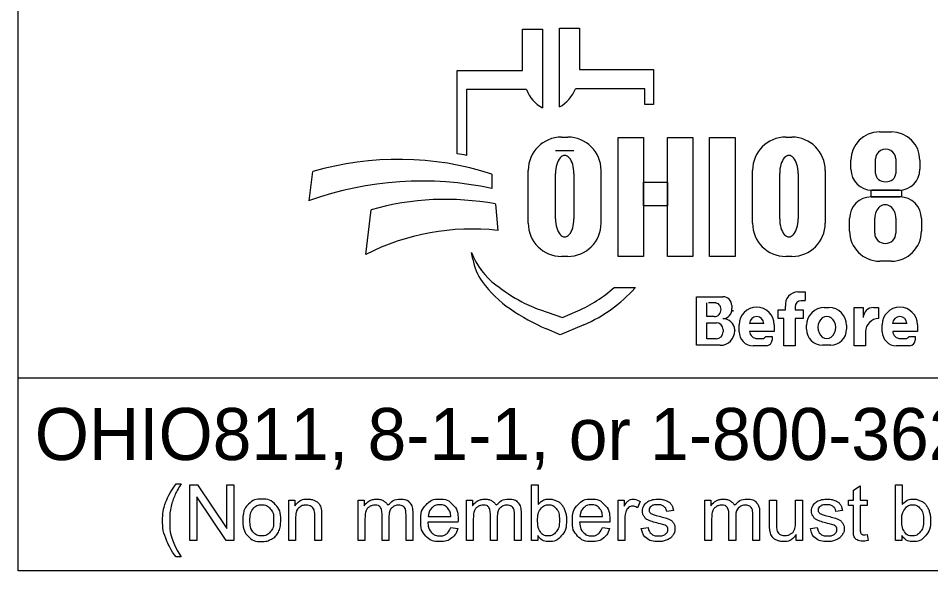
# Model space of a CAD drawing. Extents: x 0 to 45, y -99 to 22.
# Drawn here: x 2.978 to 5.431, y 2.462 to 3.948 of the extents above; entities that cross this region are included whole.
import ezdxf

# ---------------------------------------------------------------- set-up
doc = ezdxf.new("R2010")
doc.units = 0
doc.layers.add('SH_Cut_Line', color=7, linetype='Continuous')
doc.layers.add('SH_Text', color=7, linetype='Continuous')

msp = doc.modelspace()

# ---------------------------------------------------------------- linework, layer by layer
at = {"layer": 'SH_Cut_Line'}
for p, q in [((2.9775, 2.4619), (2.9775, 4.7994)), ((7.2275, 2.9798), (2.9775, 2.9798)), ((7.2275, 2.4619), (2.9775, 2.4619))]:
    msp.add_line(p, q, dxfattribs=at)
at = {"layer": 'SH_Text'}
for p, q in [((4.3335, 3.8074), (4.3335, 3.9189)), ((4.3335, 3.9189), (4.3872, 3.9189)), ((4.3872, 3.9189), (4.3872, 3.7068)), ((4.4329, 3.7092), (4.4329, 3.9212)), ((4.4329, 3.9212), (4.4865, 3.9212)), ((4.4865, 3.9212), (4.4865, 3.8097)), ((4.1576, 3.5835), (4.1576, 3.8074)), ((4.1576, 3.8074), (4.3335, 3.8074)), ((4.4865, 3.8097), (4.6857, 3.8097)), ((4.6857, 3.8097), (4.6857, 3.7159)), ((4.1828, 3.756), (4.1828, 3.5791)), ((4.3439, 3.756), (4.1828, 3.756)), ((4.6625, 3.7583), (4.4761, 3.7583)), ((4.6625, 3.7159), (4.6625, 3.7583)), ((4.6857, 3.7159), (4.6625, 3.7159)), ((5.2931, 3.6422), (5.3258, 3.6422)), ((4.4385, 3.6282), (4.4551, 3.6282)), ((5.0416, 3.6282), (5.0581, 3.6282)), ((4.4718, 3.5912), (4.422, 3.5912)), ((5.2168, 3.5416), (5.2168, 3.5659)), ((5.283, 3.5302), (5.283, 3.5695)), ((5.3371, 3.5695), (5.3371, 3.5302)), ((5.4022, 3.5659), (5.4022, 3.5416)), ((3.7602, 3.4572), (3.7696, 3.5353)), ((4.3491, 3.3967), (4.3491, 3.5388)), ((4.5445, 3.5388), (4.5445, 3.3967)), ((4.9521, 3.3967), (4.9521, 3.5388)), ((5.1476, 3.5388), (5.1476, 3.3967)), ((4.2509, 3.5289), (4.2509, 3.49)), ((4.422, 3.4081), (4.422, 3.5305)), ((4.4718, 3.5305), (4.4718, 3.4081)), ((5.025, 3.4081), (5.025, 3.5305)), ((5.0748, 3.5305), (5.0748, 3.4081)), ((5.3462, 3.4856), (5.2728, 3.4856)), ((5.271, 3.4673), (5.3483, 3.4673)), ((4.2608, 3.4482), (4.2671, 3.3773)), ((3.912, 3.3127), (3.9267, 3.4328)), ((5.2131, 3.3754), (5.2131, 3.4094)), ((5.2806, 3.3694), (5.2806, 3.4103)), ((5.3374, 3.4103), (5.3374, 3.3694)), ((5.4062, 3.4094), (5.4062, 3.3754)), ((4.1997, 3.2998), (4.1967, 3.3177)), ((4.4551, 3.3073), (4.4385, 3.3073)), ((5.0581, 3.3073), (5.0416, 3.3073)), ((5.3252, 3.2944), (5.2941, 3.2944)), ((4.58, 3.2239), (4.6375, 3.2239)), ((4.8013, 3.0682), (4.8013, 3.1989)), ((4.8013, 3.1989), (4.8725, 3.1989)), ((5.0739, 3.2117), (5.0934, 3.2117)), ((5.0934, 3.2117), (5.0934, 3.1887)), ((4.8293, 3.1454), (4.8293, 3.1823)), ((4.8545, 3.1823), (4.8332, 3.1823)), ((4.8963, 3.1751), (4.8963, 3.1672)), ((5.0406, 3.1633), (5.0406, 3.1737)), ((5.0667, 3.1717), (5.0667, 3.1633)), ((5.0934, 3.1882), (5.0832, 3.1882)), ((5.1451, 3.1699), (5.1573, 3.1699)), ((5.2254, 3.067), (5.2254, 3.1696)), ((5.2254, 3.1696), (5.2499, 3.1696)), ((5.2499, 3.1696), (5.2499, 3.1428)), ((5.2772, 3.1696), (5.291, 3.1696)), ((5.291, 3.1696), (5.291, 3.14)), ((4.3816, 3.1635), (4.441, 3.143)), ((4.441, 3.143), (4.4821, 3.1609)), ((4.8487, 3.1454), (4.8293, 3.1454)), ((5.0213, 3.1403), (5.0213, 3.1633)), ((5.0213, 3.1633), (5.0406, 3.1633)), ((5.0667, 3.1633), (5.0883, 3.1633)), ((5.0883, 3.1633), (5.0883, 3.1403)), ((4.4983, 3.1235), (4.435, 3.096)), ((4.8293, 3.086), (4.8293, 3.1288)), ((4.8293, 3.1288), (4.8548, 3.1288)), ((4.9159, 3.1049), (4.9159, 3.1234)), ((4.9824, 3.1273), (4.9439, 3.1273)), ((5.0104, 3.1234), (5.0104, 3.1057)), ((5.0362, 3.1403), (5.0213, 3.1403)), ((5.0362, 3.067), (5.0362, 3.1403)), ((5.0883, 3.1403), (5.0667, 3.1403)), ((5.0667, 3.1403), (5.0667, 3.067)), ((5.0973, 3.1113), (5.0973, 3.1221)), ((5.2051, 3.1221), (5.2051, 3.1113)), ((5.3008, 3.1049), (5.3008, 3.1234)), ((5.3674, 3.1273), (5.3288, 3.1273)), ((5.3953, 3.1234), (5.3953, 3.1057)), ((4.435, 3.096), (4.3976, 3.1125)), ((4.8729, 3.1107), (4.8729, 3.1044)), ((4.9043, 3.1078), (4.9043, 3.1075)), ((5.0104, 3.1057), (4.944, 3.1057)), ((4.9876, 3.092), (5.0045, 3.092)), ((5.0045, 3.092), (5.0045, 3.0822)), ((5.2559, 3.1051), (5.2559, 3.067)), ((5.3953, 3.1057), (5.3289, 3.1057)), ((5.3725, 3.092), (5.3894, 3.092)), ((5.3894, 3.092), (5.3894, 3.0822)), ((4.865, 3.0682), (4.8013, 3.0682)), ((4.8546, 3.086), (4.8293, 3.086)), ((4.9649, 3.0864), (4.979, 3.0864)), ((5.1623, 3.0685), (5.1401, 3.0685)), ((5.3498, 3.0864), (5.3639, 3.0864)), ((4.9892, 3.067), (4.9538, 3.067)), ((5.0667, 3.067), (5.0362, 3.067)), ((5.2559, 3.067), (5.2254, 3.067)), ((5.3742, 3.067), (5.3388, 3.067))]:
    msp.add_line(p, q, dxfattribs=at)
for points in [[(4.591, 3.6272), (4.6589, 3.6272), (4.6589, 3.3072), (4.591, 3.3072)], [(4.7231, 3.6272), (4.7911, 3.6272), (4.7911, 3.3072), (4.7231, 3.3072)], [(4.8364, 3.6272), (4.9052, 3.6272), (4.9052, 3.3072), (4.8364, 3.3072)], [(4.6589, 3.5073), (4.7231, 3.5073), (4.7231, 3.4433), (4.6589, 3.4433)], [(5.2706, 3.4857), (5.3523, 3.4857), (5.3523, 3.4672), (5.2706, 3.4672)]]:
    msp.add_lwpolyline(points, close=True, dxfattribs=at)
for points in [[(3.4021, 2.6957), (3.4153, 2.6957)], [(3.4389, 2.543), (3.4389, 2.6932), (3.4592, 2.6932), (3.5382, 2.5753), (3.5382, 2.6932), (3.5572, 2.6932), (3.5572, 2.543), (3.5369, 2.543), (3.4579, 2.661), (3.4579, 2.543), (3.4389, 2.543)], [(4.3743, 2.543), (4.3573, 2.543), (4.3573, 2.6932), (4.3757, 2.6932), (4.3757, 2.6397)], [(5.2233, 2.5749), (5.2233, 2.6376), (5.2097, 2.6376), (5.2097, 2.6519), (5.2233, 2.6519), (5.2233, 2.6788), (5.2417, 2.6899), (5.2417, 2.6519), (5.2601, 2.6519), (5.2601, 2.6376), (5.2417, 2.6376), (5.2417, 2.5738)], [(5.3534, 2.543), (5.3363, 2.543), (5.3363, 2.6932), (5.3548, 2.6932), (5.3548, 2.6397)], [(3.7048, 2.543), (3.7048, 2.6519), (3.7214, 2.6519), (3.7214, 2.6364)], [(3.8912, 2.543), (3.8912, 2.6519), (3.9077, 2.6519), (3.9077, 2.6365)], [(4.1826, 2.543), (4.1826, 2.6519), (4.1991, 2.6519), (4.1991, 2.6365)], [(4.5904, 2.543), (4.5904, 2.6519), (4.607, 2.6519), (4.607, 2.6354)], [(4.8236, 2.543), (4.8236, 2.6519), (4.8401, 2.6519), (4.8401, 2.6365)], [(4.9979, 2.5845), (4.9979, 2.6519), (5.0164, 2.6519), (5.0164, 2.5916)], [(5.0676, 2.5936), (5.0676, 2.6519), (5.0861, 2.6519), (5.0861, 2.543), (5.0696, 2.543)], [(4.6495, 2.6484), (4.643, 2.6313)], [(3.7233, 2.6024), (3.7233, 2.543), (3.7048, 2.543)], [(3.7932, 2.6099), (3.7932, 2.543), (3.7748, 2.543), (3.7748, 2.6092)], [(3.9743, 2.6062), (3.9743, 2.543), (3.9559, 2.543), (3.9559, 2.6137)], [(4.0388, 2.6177), (4.0388, 2.543), (4.0203, 2.543), (4.0203, 2.6115)], [(4.0799, 2.6078), (4.1406, 2.6078)], [(4.2657, 2.6062), (4.2657, 2.543), (4.2473, 2.543), (4.2473, 2.6137)], [(4.3301, 2.6177), (4.3301, 2.543), (4.3117, 2.543), (4.3117, 2.6115)], [(4.4879, 2.6078), (4.5486, 2.6078)], [(4.7394, 2.6237), (4.7213, 2.6213)], [(4.9067, 2.6062), (4.9067, 2.543), (4.8883, 2.543), (4.8883, 2.6137)], [(4.9711, 2.6177), (4.9711, 2.543), (4.9527, 2.543), (4.9527, 2.6115)], [(5.194, 2.6237), (5.1759, 2.6213)], [(3.9097, 2.5994), (3.9097, 2.543), (3.8912, 2.543)], [(4.16, 2.5927), (4.0788, 2.5927)], [(4.1404, 2.5782), (4.1595, 2.5758)], [(4.201, 2.5994), (4.201, 2.543), (4.1826, 2.543)], [(4.568, 2.5927), (4.4868, 2.5927)], [(4.5484, 2.5782), (4.5675, 2.5758)], [(4.6088, 2.6), (4.6088, 2.543), (4.5904, 2.543)], [(4.653, 2.5755), (4.6712, 2.5784)], [(4.842, 2.5994), (4.842, 2.543), (4.8236, 2.543)], [(5.1076, 2.5755), (5.1258, 2.5784)], [(4.3743, 2.5567), (4.3743, 2.543)], [(5.0696, 2.543), (5.0696, 2.5591)], [(5.2601, 2.5595), (5.2628, 2.5432)], [(5.3534, 2.5567), (5.3534, 2.543)], [(3.4153, 2.4989), (3.4021, 2.4989)]]:
    msp.add_lwpolyline(points, dxfattribs=at)
for centre, radius, start, end in [((4.4353, 3.7927), 0.0985, 201.9296, 240.7469), ((4.3847, 3.7951), 0.0985, 299.2531, 338.0704), ((5.2931, 3.5659), 0.0763, 90, 180), ((5.3258, 3.5659), 0.0763, 0, 90), ((4.4385, 3.5388), 0.0895, 90, 180), ((4.4551, 3.5388), 0.0895, 0, 90), ((5.0416, 3.5388), 0.0895, 90, 180), ((5.0581, 3.5388), 0.0895, 0, 90), ((4.0295, 2.7745), 0.8191, 79.2074, 81.0007), ((3.9997, 2.7493), 0.8191, 72.1402, 106.3144), ((5.2728, 3.5416), 0.056, 180, 270), ((5.3462, 3.5416), 0.056, 270, 0), ((4.0628, 2.6182), 0.8919, 77.8238, 109.8274), ((4.1267, 2.7285), 0.7322, 79.44, 105.8467), ((5.271, 3.4094), 0.0579, 90, 180), ((5.3483, 3.4094), 0.0579, 0, 90), ((4.4385, 3.3967), 0.0895, 180, 270), ((4.4551, 3.3967), 0.0895, 270, 0), ((5.0416, 3.3967), 0.0895, 180, 270), ((5.0581, 3.3967), 0.0895, 270, 0), ((4.1987, 2.7453), 0.6357, 83.8248, 116.8021), ((5.2941, 3.3754), 0.081, 180, 270), ((5.3252, 3.3754), 0.081, 270, 0), ((4.3841, 3.3898), 0.2008, 201.0457, 232.5314), ((4.341, 3.3239), 0.1433, 189.6817, 216.0884), ((4.4747, 3.4213), 0.3088, 216.0884, 235.7167), ((4.5766, 3.641), 0.5173, 232.5314, 241.794), ((4.3387, 3.4913), 0.3602, 293.4582, 312.0712), ((4.3387, 3.4913), 0.401, 293.4582, 317.8286), ((4.8725, 3.1751), 0.0238, 0, 90), ((5.0739, 3.1781), 0.0335, 90, 187.5187), ((4.6412, 3.6656), 0.6044, 235.7167, 246.2325), ((4.4914, 3.4822), 0.3371, 241.794, 250.9821), ((4.8505, 3.1654), 0.0169, 357.8325, 90), ((4.8721, 3.1644), 0.0243, 270, 6.6529), ((4.9631, 3.1234), 0.0473, 0, 180), ((5.0832, 3.1717), 0.0165, 90, 180), ((5.1451, 3.1221), 0.0478, 90, 180), ((5.1573, 3.1221), 0.0478, 0, 90), ((5.2768, 3.1428), 0.0269, 89.2449, 180), ((5.3481, 3.1234), 0.0473, 0, 180), ((4.8487, 3.1641), 0.0187, 270, 2.0582), ((4.8827, 3.1629), 0.0175, 347.4023, 0), ((4.9632, 3.1263), 0.0193, 2.9632, 177.0368), ((5.3481, 3.1263), 0.0193, 2.9632, 177.0368), ((4.8548, 3.1107), 0.0181, 0, 90), ((4.8722, 3.108), 0.0321, 4.0748, 90), ((5.2908, 3.1051), 0.0349, 89.6033, 180), ((4.8546, 3.1044), 0.0184, 270, 0), ((4.865, 3.1075), 0.0393, 270, 0), ((4.8714, 3.1078), 0.033, 0, 11.7502), ((4.9538, 3.1049), 0.038, 180, 270), ((4.9649, 3.1074), 0.021, 184.827, 270), ((4.979, 3.0958), 0.00938, 270, 335.9979), ((5.1401, 3.1113), 0.0428, 180, 270), ((5.1623, 3.1113), 0.0428, 270, 0), ((5.3388, 3.1049), 0.038, 180, 270), ((5.3498, 3.1074), 0.021, 184.827, 270), ((5.3639, 3.0958), 0.00938, 270, 335.9979), ((4.9892, 3.0822), 0.0152, 270, 0), ((5.3742, 3.0822), 0.0152, 270, 0)]:
    msp.add_arc(centre, radius, start, end, dxfattribs=at)
for centre, major_axis, ratio, start_param, end_param in [((5.31, 3.5695), (0.0271, 0), 0.969373, 0, 3.141593), ((4.4469, 3.5305), (0, 0.0484), 0.514403, 4.712389, 7.853982), ((5.0499, 3.5305), (0, 0.0484), 0.514403, 4.712389, 7.853982), ((5.31, 3.5302), (0.0271, 0), 0.818453, 3.141593, 6.283185), ((5.309, 3.4103), (0, 0.0358), 0.794529, 4.712389, 7.853982), ((4.4469, 3.4081), (0, 0.0484), 0.514403, 1.570796, 4.712389), ((5.0499, 3.4081), (0, 0.0484), 0.514403, 1.570796, 4.712389), ((5.309, 3.3694), (0.0284, 0), 0.959837, 3.141593, 6.283185), ((5.1517, 3.1167), (0, 0.029), 0.832186, 4.712389, 7.853982), ((5.1517, 3.1167), (0, 0.0302), 0.797287, 1.570796, 4.712389)]:
    msp.add_ellipse(centre, major_axis=major_axis, ratio=ratio, start_param=start_param, end_param=end_param, dxfattribs=at)
for points in [[(3.4021, 2.4989), (3.3869, 2.5181), (3.3763, 2.5439), (3.3657, 2.5697), (3.3657, 2.5974), (3.3657, 2.6218), (3.3736, 2.6441), (3.3829, 2.67), (3.4021, 2.6957)], [(3.4153, 2.6957), (3.4029, 2.6744), (3.3989, 2.6653), (3.3927, 2.6511), (3.3891, 2.6358), (3.3847, 2.6166), (3.3847, 2.5973), (3.3847, 2.548), (3.4153, 2.4989)], [(3.5814, 2.5974), (3.5814, 2.6277), (3.5981, 2.6422), (3.6122, 2.6543), (3.6323, 2.6543), (3.6547, 2.6543), (3.669, 2.6396), (3.6832, 2.6249), (3.6832, 2.599), (3.6832, 2.578), (3.6769, 2.566), (3.6706, 2.5539), (3.6586, 2.5473), (3.6466, 2.5406), (3.6323, 2.5406), (3.6095, 2.5406), (3.5954, 2.5553), (3.5814, 2.5699), (3.5814, 2.5974)], [(3.7214, 2.6364), (3.7334, 2.6543), (3.756, 2.6543), (3.7659, 2.6543), (3.7741, 2.6507), (3.7823, 2.6472), (3.7864, 2.6415), (3.7905, 2.6357), (3.7922, 2.6278), (3.7932, 2.6227), (3.7932, 2.6099)], [(3.9077, 2.6365), (3.9128, 2.6445), (3.9214, 2.6494), (3.9299, 2.6543), (3.9407, 2.6543), (3.9528, 2.6543), (3.9606, 2.6492), (3.9683, 2.6442), (3.9715, 2.6352), (3.9844, 2.6543), (4.0051, 2.6543), (4.0213, 2.6543), (4.03, 2.6453), (4.0388, 2.6363), (4.0388, 2.6177)], [(4.1595, 2.5758), (4.155, 2.5591), (4.1428, 2.5498), (4.1306, 2.5406), (4.1117, 2.5406), (4.0878, 2.5406), (4.0738, 2.5553), (4.0598, 2.57), (4.0598, 2.5965), (4.0598, 2.624), (4.074, 2.6391), (4.0881, 2.6543), (4.1106, 2.6543), (4.1324, 2.6543), (4.1463, 2.6394), (4.1601, 2.6246), (4.1601, 2.5976), (4.1601, 2.596), (4.16, 2.5927)], [(4.1991, 2.6365), (4.2042, 2.6445), (4.2127, 2.6494), (4.2212, 2.6543), (4.2321, 2.6543), (4.2442, 2.6543), (4.2519, 2.6492), (4.2597, 2.6442), (4.2628, 2.6352), (4.2758, 2.6543), (4.2965, 2.6543), (4.3127, 2.6543), (4.3214, 2.6453), (4.3301, 2.6363), (4.3301, 2.6177)], [(4.3757, 2.6397), (4.3874, 2.6543), (4.4055, 2.6543), (4.4155, 2.6543), (4.4245, 2.6502), (4.4335, 2.6462), (4.4392, 2.6389), (4.445, 2.6315), (4.4483, 2.6212), (4.4516, 2.6109), (4.4516, 2.5991), (4.4516, 2.5711), (4.4378, 2.5559), (4.4239, 2.5406), (4.4046, 2.5406), (4.3853, 2.5406), (4.3743, 2.5567)], [(4.5675, 2.5758), (4.563, 2.5591), (4.5508, 2.5498), (4.5386, 2.5406), (4.5196, 2.5406), (4.4958, 2.5406), (4.4818, 2.5553), (4.4678, 2.57), (4.4678, 2.5965), (4.4678, 2.624), (4.482, 2.6391), (4.4961, 2.6543), (4.5186, 2.6543), (4.5404, 2.6543), (4.5543, 2.6394), (4.5681, 2.6246), (4.5681, 2.5976), (4.5681, 2.596), (4.568, 2.5927)], [(4.607, 2.6354), (4.6133, 2.6469), (4.6187, 2.6506), (4.6241, 2.6543), (4.6305, 2.6543), (4.6398, 2.6543), (4.6495, 2.6484)], [(4.6712, 2.5784), (4.6727, 2.5674), (4.6798, 2.5616), (4.6868, 2.5557), (4.6995, 2.5557), (4.7122, 2.5557), (4.7184, 2.5609), (4.7245, 2.5661), (4.7245, 2.5731), (4.7245, 2.5793), (4.7191, 2.5829), (4.7153, 2.5854), (4.7002, 2.5892), (4.6799, 2.5943), (4.672, 2.598), (4.6642, 2.6018), (4.6601, 2.6084), (4.6561, 2.615), (4.6561, 2.623), (4.6561, 2.6302), (4.6594, 2.6364), (4.6628, 2.6426), (4.6685, 2.6467), (4.6728, 2.6499), (4.6803, 2.6521), (4.6877, 2.6543), (4.6962, 2.6543), (4.709, 2.6543), (4.7187, 2.6506), (4.7284, 2.6469), (4.733, 2.6406), (4.7377, 2.6343), (4.7394, 2.6237)], [(4.8401, 2.6365), (4.8452, 2.6445), (4.8537, 2.6494), (4.8622, 2.6543), (4.8731, 2.6543), (4.8852, 2.6543), (4.8929, 2.6492), (4.9007, 2.6442), (4.9038, 2.6352), (4.9168, 2.6543), (4.9375, 2.6543), (4.9537, 2.6543), (4.9624, 2.6453), (4.9711, 2.6363), (4.9711, 2.6177)], [(5.1258, 2.5784), (5.1273, 2.5674), (5.1343, 2.5616), (5.1414, 2.5557), (5.154, 2.5557), (5.1668, 2.5557), (5.1729, 2.5609), (5.1791, 2.5661), (5.1791, 2.5731), (5.1791, 2.5793), (5.1736, 2.5829), (5.1698, 2.5854), (5.1548, 2.5892), (5.1345, 2.5943), (5.1266, 2.598), (5.1188, 2.6018), (5.1147, 2.6084), (5.1107, 2.615), (5.1107, 2.623), (5.1107, 2.6302), (5.114, 2.6364), (5.1173, 2.6426), (5.1231, 2.6467), (5.1274, 2.6499), (5.1348, 2.6521), (5.1423, 2.6543), (5.1508, 2.6543), (5.1636, 2.6543), (5.1733, 2.6506), (5.183, 2.6469), (5.1876, 2.6406), (5.1922, 2.6343), (5.194, 2.6237)], [(5.3548, 2.6397), (5.3664, 2.6543), (5.3846, 2.6543), (5.3946, 2.6543), (5.4036, 2.6502), (5.4125, 2.6462), (5.4183, 2.6389), (5.4241, 2.6315), (5.4274, 2.6212), (5.4306, 2.6109), (5.4306, 2.5991), (5.4306, 2.5711), (5.4168, 2.5559), (5.403, 2.5406), (5.3836, 2.5406), (5.3644, 2.5406), (5.3534, 2.5567)], [(3.6003, 2.5974), (3.6003, 2.5765), (3.6094, 2.5661), (3.6185, 2.5557), (3.6323, 2.5557), (3.646, 2.5557), (3.6551, 2.5662), (3.6642, 2.5766), (3.6642, 2.5981), (3.6642, 2.6182), (3.6551, 2.6286), (3.6459, 2.639), (3.6323, 2.639), (3.6185, 2.639), (3.6094, 2.6287), (3.6003, 2.6183), (3.6003, 2.5974)], [(3.7748, 2.6092), (3.7748, 2.6204), (3.7726, 2.626), (3.7705, 2.6316), (3.765, 2.6349), (3.7595, 2.6382), (3.7521, 2.6382), (3.7404, 2.6382), (3.7318, 2.6308), (3.7233, 2.6233), (3.7233, 2.6024)], [(3.9559, 2.6137), (3.9559, 2.626), (3.9514, 2.6321), (3.9469, 2.6382), (3.9366, 2.6382), (3.9288, 2.6382), (3.9222, 2.6342), (3.9156, 2.6301), (3.9126, 2.6222), (3.9097, 2.6143), (3.9097, 2.5994)], [(4.0203, 2.6115), (4.0203, 2.6226), (4.0185, 2.6274), (4.0168, 2.6323), (4.012, 2.6353), (4.0073, 2.6382), (4.001, 2.6382), (3.9895, 2.6382), (3.9819, 2.6306), (3.9743, 2.623), (3.9743, 2.6062)], [(4.1406, 2.6078), (4.1394, 2.6216), (4.1337, 2.6285), (4.1249, 2.6392), (4.1108, 2.6392), (4.0981, 2.6392), (4.0894, 2.6306), (4.0808, 2.6221), (4.0799, 2.6078)], [(4.2473, 2.6137), (4.2473, 2.626), (4.2428, 2.6321), (4.2383, 2.6382), (4.228, 2.6382), (4.2202, 2.6382), (4.2136, 2.6342), (4.207, 2.6301), (4.204, 2.6222), (4.201, 2.6143), (4.201, 2.5994)], [(4.3117, 2.6115), (4.3117, 2.6226), (4.3099, 2.6274), (4.3081, 2.6323), (4.3034, 2.6353), (4.2987, 2.6382), (4.2923, 2.6382), (4.2809, 2.6382), (4.2733, 2.6306), (4.2657, 2.623), (4.2657, 2.6062)], [(4.3741, 2.5983), (4.3741, 2.5787), (4.3794, 2.57), (4.3881, 2.5557), (4.4029, 2.5557), (4.415, 2.5557), (4.4238, 2.5662), (4.4326, 2.5767), (4.4326, 2.5976), (4.4326, 2.6189), (4.4241, 2.629), (4.4157, 2.6392), (4.4038, 2.6392), (4.3917, 2.6392), (4.3829, 2.6287), (4.3741, 2.6182), (4.3741, 2.5983)], [(4.5486, 2.6078), (4.5474, 2.6216), (4.5417, 2.6285), (4.5328, 2.6392), (4.5188, 2.6392), (4.5061, 2.6392), (4.4974, 2.6306), (4.4888, 2.6221), (4.4879, 2.6078)], [(4.643, 2.6313), (4.6363, 2.6353), (4.6295, 2.6353), (4.6235, 2.6353), (4.6187, 2.6316), (4.6139, 2.628), (4.6119, 2.6215), (4.6088, 2.6117), (4.6088, 2.6)], [(4.7213, 2.6213), (4.7201, 2.6297), (4.7142, 2.6344), (4.7083, 2.6392), (4.6975, 2.6392), (4.6848, 2.6392), (4.6794, 2.635), (4.6739, 2.6308), (4.6739, 2.6251), (4.6739, 2.6215), (4.6762, 2.6186), (4.6785, 2.6157), (4.6833, 2.6137), (4.686, 2.6127), (4.6996, 2.609), (4.7192, 2.6038), (4.7269, 2.6005), (4.7347, 2.5971), (4.7391, 2.5908), (4.7435, 2.5844), (4.7435, 2.575), (4.7435, 2.5658), (4.7381, 2.5577), (4.7327, 2.5495), (4.7226, 2.5451), (4.7124, 2.5406), (4.6996, 2.5406), (4.6784, 2.5406), (4.6672, 2.5494), (4.6561, 2.5582), (4.653, 2.5755)], [(4.8883, 2.6137), (4.8883, 2.626), (4.8838, 2.6321), (4.8793, 2.6382), (4.869, 2.6382), (4.8612, 2.6382), (4.8546, 2.6342), (4.848, 2.6301), (4.845, 2.6222), (4.842, 2.6143), (4.842, 2.5994)], [(4.9527, 2.6115), (4.9527, 2.6226), (4.9509, 2.6274), (4.9491, 2.6323), (4.9444, 2.6353), (4.9397, 2.6382), (4.9333, 2.6382), (4.9219, 2.6382), (4.9143, 2.6306), (4.9067, 2.623), (4.9067, 2.6062)], [(5.1759, 2.6213), (5.1747, 2.6297), (5.1688, 2.6344), (5.1629, 2.6392), (5.1521, 2.6392), (5.1394, 2.6392), (5.1339, 2.635), (5.1285, 2.6308), (5.1285, 2.6251), (5.1285, 2.6215), (5.1308, 2.6186), (5.133, 2.6157), (5.1378, 2.6137), (5.1406, 2.6127), (5.1542, 2.609), (5.1737, 2.6038), (5.1815, 2.6005), (5.1893, 2.5971), (5.1937, 2.5908), (5.1981, 2.5844), (5.1981, 2.575), (5.1981, 2.5658), (5.1927, 2.5577), (5.1873, 2.5495), (5.1772, 2.5451), (5.167, 2.5406), (5.1542, 2.5406), (5.1329, 2.5406), (5.1218, 2.5494), (5.1107, 2.5582), (5.1076, 2.5755)], [(5.3532, 2.5983), (5.3532, 2.5787), (5.3585, 2.57), (5.3672, 2.5557), (5.382, 2.5557), (5.3941, 2.5557), (5.4029, 2.5662), (5.4116, 2.5767), (5.4116, 2.5976), (5.4116, 2.6189), (5.4032, 2.629), (5.3948, 2.6392), (5.3828, 2.6392), (5.3708, 2.6392), (5.362, 2.6287), (5.3532, 2.6182), (5.3532, 2.5983)], [(4.0788, 2.5927), (4.0799, 2.5748), (4.089, 2.5653), (4.0981, 2.5557), (4.1117, 2.5557), (4.1219, 2.5557), (4.1291, 2.5611), (4.1362, 2.5664), (4.1404, 2.5782)], [(4.4868, 2.5927), (4.4879, 2.5748), (4.497, 2.5653), (4.5061, 2.5557), (4.5197, 2.5557), (4.5299, 2.5557), (4.537, 2.5611), (4.5442, 2.5664), (4.5484, 2.5782)], [(5.0696, 2.5591), (5.0569, 2.5406), (5.0351, 2.5406), (5.0255, 2.5406), (5.0171, 2.5443), (5.0088, 2.548), (5.0047, 2.5536), (5.0007, 2.5592), (4.9991, 2.5673), (4.9979, 2.5727), (4.9979, 2.5845)], [(5.0164, 2.5916), (5.0164, 2.5771), (5.0175, 2.5721), (5.0192, 2.5648), (5.0249, 2.5607), (5.0305, 2.5565), (5.0388, 2.5565), (5.0471, 2.5565), (5.0543, 2.5608), (5.0616, 2.565), (5.0646, 2.5724), (5.0676, 2.5797), (5.0676, 2.5936)], [(5.2628, 2.5432), (5.255, 2.5415), (5.2488, 2.5415), (5.2388, 2.5415), (5.2333, 2.5447), (5.2278, 2.5479), (5.2255, 2.5531), (5.2233, 2.5583), (5.2233, 2.5749)], [(5.2417, 2.5738), (5.2417, 2.5659), (5.2427, 2.5636), (5.2436, 2.5614), (5.2458, 2.56), (5.248, 2.5587), (5.2521, 2.5587), (5.2551, 2.5587), (5.2601, 2.5595)]]:
    msp.add_open_spline(points, degree=3, dxfattribs=at)

# ---------------------------------------------------------------- texts
msp.add_text('OHIO811, 8-1-1, or 1-800-362-2764', height=0.14, dxfattribs=at).set_placement((3.022, 2.7597))

doc.saveas('drawing.dxf')
